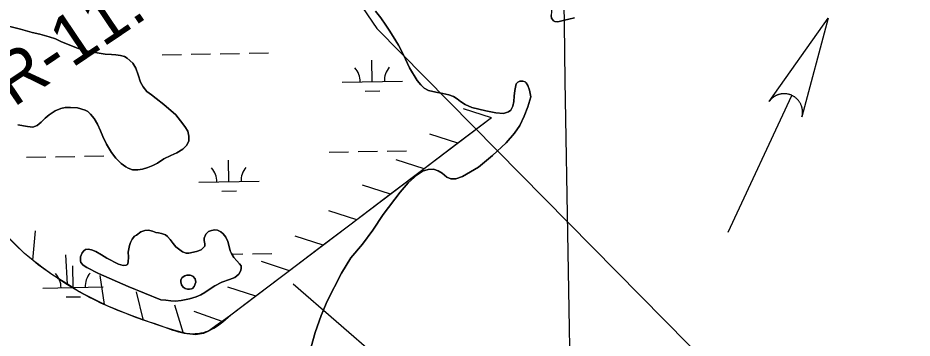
# Model space of a CAD drawing. Extents: x 3892998 to 3931244, y 278583 to 304547.
# Drawn here: x 3912138 to 3913620, y 293140 to 293671 of the extents above; entities that cross this region are included whole.
import ezdxf

# ---------------------------------------------------------------- set-up
doc = ezdxf.new("R2010")
doc.units = 0
for name, color, linetype in [('V-GRID-MAJR', 7, 'Continuous'), ('V-RIVR-RANG-IDEN', 7, 'Continuous'), ('V-RRAP-FSHR', 7, 'Continuous'), ('V-STRM-FLOW', 7, 'Continuous'), ('V-TOPO-SHOR', 7, 'Continuous'), ('V-UTIL-IDEN', 7, 'Continuous'), ('V-UTIL-LINE', 7, 'Continuous'), ('V-WETL-SWMP', 7, 'Continuous')]:
    doc.layers.add(name, color=color, linetype=linetype)

msp = doc.modelspace()

# ---------------------------------------------------------------- linework, layer by layer
at = {"layer": 'V-GRID-MAJR'}
msp.add_spline([(3913205.694, 284291.167), (3913100.856, 290347.625), (3912995.9590000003, 296407.553), (3912891.061, 302467.47500000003), (3912891.001, 302470.95)], degree=3, dxfattribs=at)
at = {"layer": 'V-RRAP-FSHR'}
for p, q in [((3912922.664, 293505.93), (3912876.1720000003, 293520.863)), ((3912866.903, 293463.615), (3912820.4110000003, 293478.548)), ((3912811.1410000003, 293421.3), (3912764.65, 293436.233)), ((3912755.38, 293378.985), (3912708.889, 293393.918)), ((3912699.619, 293336.67100000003), (3912653.127, 293351.604)), ((3912162.119, 293269.672), (3912166.453, 293318.31)), ((3912643.809, 293294.42), (3912597.34, 293309.424)), ((3912219.542, 293229.782), (3912217.167, 293278.555)), ((3912587.983, 293252.19), (3912541.514, 293267.195)), ((3912280.844, 293196.12200000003), (3912274.079, 293244.482)), ((3912345.699, 293169.841), (3912334.42, 293217.351)), ((3912532.157, 293209.961), (3912485.688, 293224.965)), ((3912412.31, 293148.282), (3912397.573, 293194.836)), ((3912476.032, 293168.138), (3912430.011, 293184.461))]:
    msp.add_line(p, q, dxfattribs=at)
for points in [[(3912922.663, 293505.929), (3912685.523, 293325.974), (3912490.434, 293178.4)], [(3912922.663, 293505.929), (3912866.9020000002, 293463.614)], [(3912866.903, 293463.615), (3912811.14, 293421.299)], [(3912811.1410000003, 293421.3), (3912755.379, 293378.985)], [(3912755.38, 293378.985), (3912699.6180000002, 293336.67)], [(3912699.619, 293336.67100000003), (3912685.523, 293325.974), (3912643.808, 293294.419)], [(3912162.119, 293269.672), (3912148.705, 293280.964), (3912127.836, 293301.326), (3912111.333, 293317.787)], [(3912643.809, 293294.42), (3912587.9820000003, 293252.19)], [(3912219.542, 293229.782), (3912195.3680000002, 293245.012), (3912171.199, 293262.028), (3912162.1180000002, 293269.673)], [(3912587.983, 293252.19), (3912532.156, 293209.96)], [(3912280.844, 293196.12200000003), (3912239.383, 293217.281), (3912219.541, 293229.782)], [(3912345.897, 293170.374), (3912333.22, 293174.792), (3912285.646, 293193.672), (3912280.844, 293196.123)], [(3912532.157, 293209.961), (3912490.434, 293178.4), (3912476.032, 293168.138), (3912471.9760000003, 293165.248), (3912453.519, 293152.096), (3912445.484, 293148.107), (3912431.725, 293146.063), (3912417.975, 293147.601), (3912412.509, 293148.988)], [(3912412.5100000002, 293148.988), (3912399.764, 293152.222), (3912381.6610000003, 293157.907), (3912345.896, 293170.374)]]:
    msp.add_lwpolyline(points, dxfattribs=at)
msp.add_spline([(3912490.434, 293178.4), (3912453.519, 293152.096), (3912417.975, 293147.601), (3912381.6610000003, 293157.907), (3912285.646, 293193.672), (3912195.3680000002, 293245.012), (3912148.705, 293280.964), (3912107.2060000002, 293321.903), (3911938.255, 293492.825), (3911757.653, 293671.213), (3911688.061, 293737.987), (3911661.12, 293770.124), (3911612.452, 293841.272)], degree=3, dxfattribs=at)
at = {"layer": 'V-STRM-FLOW'}
msp.add_line((3913315.1484675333, 293315.9066098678), (3913420.8832560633, 293542.8871559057), dxfattribs=at)
msp.add_lwpolyline([(3913383.132331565, 293532.8931758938), (3913480.6751364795, 293671.2438991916), (3913437.521222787, 293507.5572265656), (3913438.140221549, 293510.5372206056), (3913438.4522209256, 293513.4572147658), (3913438.4982208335, 293514.6402123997), (3913438.501220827, 293515.6822103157), (3913438.4562209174, 293516.9472077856), (3913438.364221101, 293518.1632053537), (3913438.2442213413, 293519.21320325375), (3913438.0212217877, 293520.6422003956), (3913437.708222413, 293522.1631973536), (3913437.4992228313, 293523.00519566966), (3913437.193223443, 293524.0831935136), (3913436.732224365, 293525.4851907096), (3913436.3262251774, 293526.5581885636), (3913435.8452261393, 293527.6941862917), (3913435.5032268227, 293528.43318481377), (3913435.104227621, 293529.23318321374), (3913434.587228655, 293530.1931812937), (3913434.0792296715, 293531.06217955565), (3913433.5452307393, 293531.91017785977), (3913433.087231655, 293532.5921764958), (3913432.3722330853, 293533.58217451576), (3913431.6502345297, 293534.5031726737), (3913431.048235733, 293535.22017123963), (3913430.3132372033, 293536.0381696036), (3913429.651238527, 293536.7271682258), (3913429.0452397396, 293537.32016703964), (3913428.5652406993, 293537.7681661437), (3913427.8102422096, 293538.4331648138), (3913427.0152437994, 293539.0901634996), (3913426.241245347, 293539.6871623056), (3913425.434246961, 293540.26816114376), (3913424.6702484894, 293540.78316011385), (3913423.8182501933, 293541.32015903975), (3913423.1052516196, 293541.7381582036), (3913422.065253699, 293542.3041570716), (3913420.8832560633, 293542.8871559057), (3913420.4982568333, 293543.0631555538), (3913419.933257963, 293543.3101550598), (3913419.2542593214, 293543.5891545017), (3913418.590260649, 293543.8441539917), (3913417.9422619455, 293544.07515352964), (3913417.3042632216, 293544.2871531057), (3913416.5442647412, 293544.52015263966), (3913416.010265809, 293544.6701523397), (3913415.2252673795, 293544.87315193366), (3913414.488268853, 293545.0421515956), (3913413.9762698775, 293545.14915138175), (3913412.6522725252, 293545.3831509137), (3913411.9392739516, 293545.48515070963), (3913411.449274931, 293545.5441505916), (3913410.636276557, 293545.62615042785), (3913409.9112780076, 293545.6801503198), (3913409.1522795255, 293545.71815024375), (3913408.2532813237, 293545.7391502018), (3913407.412283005, 293545.7331502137), (3913406.7572843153, 293545.71415025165), (3913406.197285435, 293545.68615030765), (3913405.4362869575, 293545.6311504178), (3913404.7542883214, 293545.56615054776), (3913403.966289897, 293545.4711507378), (3913403.1672914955, 293545.35415097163), (3913402.3642931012, 293545.2131512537), (3913401.351295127, 293545.0051516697), (3913400.6292965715, 293544.83515200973), (3913399.839298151, 293544.62715242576), (3913399.0692996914, 293544.4021528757), (3913398.4523009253, 293544.20515326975), (3913397.7853022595, 293543.9761537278), (3913396.804304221, 293543.60915446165), (3913396.7673042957, 293543.5941544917), (3913396.192305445, 293543.3591549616), (3913395.7693062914, 293543.1781553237), (3913395.1403075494, 293542.89415589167), (3913394.3683090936, 293542.52215663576), (3913393.762310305, 293542.2101572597), (3913393.2223113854, 293541.9181578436), (3913392.538312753, 293541.5281586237), (3913391.8903140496, 293541.1351594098), (3913391.4323149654, 293540.8451599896), (3913390.843316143, 293540.4541607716), (3913390.0473177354, 293539.8931618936), (3913389.5833186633, 293539.5481625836), (3913389.2233193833, 293539.2711631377), (3913388.896320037, 293539.0121636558), (3913388.5113208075, 293538.69816428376), (3913388.013321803, 293538.2751651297), (3913387.5243227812, 293537.8411659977), (3913387.0493237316, 293537.40116687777), (3913386.5873246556, 293536.9551677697), (3913386.004325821, 293536.36416895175), (3913385.661326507, 293536.0021696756), (3913385.1273275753, 293535.41117085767), (3913384.5273287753, 293534.71017225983), (3913384.0933296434, 293534.17417333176), (3913383.774330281, 293533.76417415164), (3913383.4823308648, 293533.3771749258), (3913383.2753312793, 293533.0931754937)], close=True, dxfattribs=at)
at = {"layer": 'V-TOPO-SHOR'}
for points in [[(3912958.6950000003, 293724.89), (3912969.6580000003, 293715.342), (3912979.329, 293706.579), (3912986.001, 293701.367), (3912992.768, 293697.541), (3913000.218, 293695.01), (3913007.861, 293693.273), (3913015.308, 293691.534), (3913018.886, 293689.969), (3913021.681, 293686.816), (3913022.304, 293682.259), (3913021.8510000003, 293675.414), (3913022.275, 293670.759), (3913025.276, 293666.612), (3913027.96, 293665.441), (3913032.521, 293665.17), (3913037.275, 293666.094), (3913043.9080000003, 293667.521), (3913050.736, 293669.348), (3913060.108, 293671.744)], [(3912988.0840000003, 293540.779), (3912985.5360000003, 293551.867), (3912983.21, 293559.586), (3912980.308, 293563.829), (3912978.3170000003, 293565.404), (3912974.94, 293566.473), (3912973.65, 293566.663), (3912969.586, 293566.342), (3912966.324, 293564.835), (3912963.864, 293561.844), (3912961.253, 293551.222), (3912960.421, 293541.401), (3912959.879, 293533.07), (3912958.144, 293524.931), (3912954.615, 293518.267), (3912950.765, 293515.666), (3912942.651, 293513.137), (3912929.761, 293513.852), (3912913.383, 293517.219), (3912889.95, 293523.023), (3912878.917, 293527.713), (3912871.153, 293532.919), (3912865.97, 293537.348), (3912859.9020000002, 293540.979), (3912851.855, 293543.705), (3912842.223, 293545.825), (3912830.312, 293548.33), (3912818.497, 293551.131), (3912811.239, 293554.855), (3912805.455, 293560.37200000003), (3912799.262, 293567.669), (3912786.544, 293588.407), (3912780.406, 293603.042), (3912774.785, 293614.408), (3912768.5670000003, 293626.266), (3912759.953, 293640.49), (3912753.145, 293651.053), (3912747.346, 293659.346), (3912739.043, 293671.488), (3912730.4450000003, 293682.73600000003)], [(3912112.904, 293660.194), (3912141.637, 293652.555), (3912161.454, 293647.238), (3912173.838, 293644.248), (3912189.4930000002, 293640.189), (3912199.702, 293636.691), (3912208.631, 293632.591), (3912218.052, 293628.693), (3912236.202, 293621.386), (3912248.789, 293617.308), (3912259.289, 293614.998), (3912272.162, 293612.805), (3912281.964, 293611.281), (3912292.8510000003, 293610.556), (3912300.073, 293610.405), (3912307.896, 293609.166)], [(3912307.896, 293609.166), (3912314.04, 293607.324), (3912318.806, 293604.58400000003), (3912327.9560000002, 293596.331), (3912332.8570000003, 293588.053), (3912336.881, 293576.998), (3912341.0100000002, 293564.955), (3912345.4110000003, 293557.069), (3912351.295, 293549.587), (3912358.848, 293543.697), (3912366.698, 293538.01), (3912379.6210000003, 293528.098), (3912399.5130000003, 293510.513), (3912407.1890000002, 293500.867), (3912414.269, 293491.612), (3912419.068, 293483.531), (3912421.197, 293475.233), (3912420.946, 293467.714), (3912417.429, 293460.471), (3912410.845, 293453.604), (3912401.086, 293447.808), (3912390.926, 293443.39), (3912379.682, 293437.881), (3912368.7460000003, 293430.691), (3912361.255, 293426.588), (3912353.163, 293423.275), (3912344.176, 293420.846), (3912336.568, 293419.316), (3912327.366, 293419.654), (3912320.131, 293422.181), (3912316.2600000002, 293424.233), (3912308.6070000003, 293429.826), (3912299.651, 293438.674), (3912292.468, 293448.324), (3912284.67, 293461.826), (3912278.356, 293474.84500000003), (3912274.64, 293483.924), (3912269.625, 293495.268), (3912264.224, 293504.732), (3912257.7490000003, 293512.013), (3912253.372, 293515.943), (3912249.202, 293518.388), (3912236.218, 293522.464), (3912224.94, 293522.889), (3912215.838, 293522.832), (3912208.5270000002, 293521.304), (3912199.252, 293517.487), (3912189.599, 293510.702), (3912182.909, 293504.922), (3912176.1240000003, 293498.352), (3912169.529, 293493.167), (3912162.2260000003, 293490.451), (3912153.219, 293491.186), (3912137.472, 293494.156)], [(3912826.327, 293420.344), (3912834.4220000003, 293417.831), (3912840.853, 293413.831), (3912848.779, 293407.18), (3912855.3000000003, 293404.263), (3912863.475, 293404.806), (3912874.686, 293408.523), (3912901.1010000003, 293423.86), (3912924.139, 293443.319), (3912947.069, 293464.352), (3912960.8680000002, 293480.006), (3912969.951, 293493.071), (3912976.951, 293508.48600000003), (3912982.767, 293524.092), (3912988.0840000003, 293540.779)], [(3912621.0640000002, 293116.151), (3912630.515, 293149.517), (3912640.589, 293177.763), (3912650.494, 293201.67100000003), (3912674.1520000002, 293248.232), (3912689.3710000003, 293273.357), (3912708.937, 293296.438), (3912726.1410000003, 293319.308), (3912743.125, 293345.627), (3912771.278, 293382.262), (3912784.683, 293397.816), (3912799.2830000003, 293411.308), (3912808.312, 293417.276), (3912817.852, 293420.293), (3912826.327, 293420.344)], [(3912374.333, 293203.89900000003), (3912320.272, 293226.222), (3912271.165, 293247.388), (3912252.0100000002, 293257.264), (3912245.852, 293261.282), (3912241.864, 293265.908), (3912241.1580000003, 293268.278), (3912241.215, 293274.907), (3912244.142, 293281.555), (3912246.691, 293285.33), (3912249.45, 293287.226), (3912254.193, 293288.148), (3912259.643, 293286.993), (3912266.588, 293283.771), (3912276.318, 293278.389), (3912284.96, 293272.802), (3912304.216, 293262.83), (3912312.242, 293260.901), (3912316.792, 293261.227), (3912319.455, 293262.628), (3912320.522, 293266.195), (3912320.663, 293275.004), (3912320.419, 293282.718), (3912322.525, 293294.109), (3912324.1780000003, 293298.771), (3912327.012, 293304.427), (3912331.0360000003, 293309.697), (3912333.9960000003, 293311.29600000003), (3912341.483, 293316.39), (3912347.9, 293318.903), (3912354.029, 293319.337), (3912360.5700000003, 293317.795), (3912366.223, 293315.751), (3912370.579, 293314.987), (3912375.435, 293314.026), (3912382.177, 293311.694), (3912385.654, 293309.14400000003), (3912389.744, 293303.825), (3912395.0300000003, 293297.032), (3912399.515, 293291.816), (3912410.648, 293283.376), (3912416.698, 293281.135), (3912420.952, 293281.36100000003), (3912433.5, 293284.011), (3912441.301, 293286.532), (3912447.2970000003, 293292.803), (3912447.572, 293296.565), (3912446.548, 293301.998), (3912446.523, 293306.156), (3912449.3510000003, 293312.701), (3912453.578, 293317.18), (3912458.315, 293319.091), (3912464.2460000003, 293320.017), (3912468.703, 293319.351), (3912474.06, 293316.81200000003), (3912478.04, 293313.375), (3912482.328, 293307.958), (3912485.4390000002, 293300.657), (3912487.669, 293292.162), (3912489.298, 293284.85000000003), (3912491.896, 293280.61100000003), (3912495.4990000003, 293274.004), (3912500.2830000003, 293268.294), (3912504.862, 293263.674), (3912507.457, 293260.127), (3912507.973, 293256.469), (3912507.111, 293252.31), (3912503.7830000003, 293246.254), (3912497.088, 293240.87), (3912488.302, 293237.55), (3912475.469, 293232.919), (3912464.228, 293227.013), (3912456.142, 293222.212), (3912447.377, 293215.827), (3912441.0670000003, 293212.226), (3912433.272, 293208.814), (3912421.816, 293205.38), (3912408.475, 293202.625), (3912398.983, 293201.874), (3912390.967, 293202.023), (3912382.65, 293203.059), (3912374.333, 293203.89900000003)], [(3912429.901, 293225.909), (3912432.328, 293233.24700000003), (3912431.2060000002, 293238.781), (3912427.321, 293243.208), (3912422.957, 293244.964), (3912417.812, 293244.833), (3912414.156, 293243.919), (3912409.722, 293241.12200000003), (3912407.668, 293237.251), (3912407.593, 293233.589), (3912408.909, 293228.453), (3912411.504, 293224.70900000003), (3912414.7830000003, 293222.452), (3912418.748, 293221.389), (3912422.309, 293221.412), (3912425.177, 293221.924), (3912426.756, 293222.427), (3912429.901, 293225.909)]]:
    msp.add_lwpolyline(points, dxfattribs=at)
at = {"layer": 'V-UTIL-LINE'}
msp.add_line((3913277.915, 292637.723), (3912593.866, 293229.884), dxfattribs=at)
msp.add_lwpolyline([(3906680.9470508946, 302363.4542383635), (3908344.9110000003, 300089.976), (3912732.592, 293653.732), (3913646.809, 292726.848), (3916248.696, 289346.047), (3918159.8680000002, 287579.415), (3921518.269458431, 284435.0583118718)], dxfattribs=at)
at = {"layer": 'V-WETL-SWMP'}
for p, q in [((3912424.976413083, 293611.1753321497), (3912456.9716198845, 293611.7291742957)), ((3912472.969223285, 293612.00609536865), (3912504.9644300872, 293612.55993751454)), ((3912520.962033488, 293612.8368585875), (3912552.9572402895, 293613.3907007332)), ((3912376.98360288, 293610.3445689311), (3912408.978809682, 293610.89841107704)), ((3912725.125799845, 293565.6213644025), (3912724.5027274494, 293601.61597205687)), ((3912675.133289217, 293564.7559860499), (3912775.1183104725, 293566.4867427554)), ((3912713.394670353, 293549.984984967), (3912737.3910754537, 293550.4003665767)), ((3912653.726642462, 293448.93614077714), (3912685.7218492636, 293449.489982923)), ((3912701.7194526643, 293449.766903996), (3912733.714659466, 293450.32074614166)), ((3912749.712262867, 293450.59766721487), (3912781.7074696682, 293451.1515093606)), ((3912151.8938219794, 293440.2493344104), (3912183.8890287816, 293440.80317655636)), ((3912199.886632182, 293441.08009762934), (3912231.8818389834, 293441.633939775)), ((3912247.879442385, 293441.9108608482), (3912279.874649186, 293442.46470299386)), ((3912487.491256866, 293399.6216240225), (3912486.8681844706, 293435.61623167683)), ((3912437.4987462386, 293398.7562456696), (3912537.483767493, 293400.4870023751)), ((3912475.760127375, 293383.98524458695), (3912499.7565324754, 293384.40062619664)), ((3912492.437372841, 293279.6182543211), (3912510.722224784, 293279.9347680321)), ((3912526.719828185, 293280.211689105), (3912558.7150349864, 293280.76553125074)), ((3912229.0507740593, 293224.3093885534), (3912228.427701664, 293260.3039962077)), ((3912179.058263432, 293223.44401020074), (3912279.0432846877, 293225.17476690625)), ((3912217.3196445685, 293208.67300911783), (3912241.3160496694, 293209.0883907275))]:
    msp.add_line(p, q, dxfattribs=at)
for points in [[(3912730.446, 293682.73600000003), (3912739.042, 293671.488), (3912747.345, 293659.346), (3912753.146, 293651.054), (3912759.952, 293640.489), (3912768.566, 293626.266), (3912774.785, 293614.408), (3912780.407, 293603.043), (3912786.545, 293588.408), (3912799.2630000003, 293567.668), (3912805.455, 293560.371), (3912811.238, 293554.855), (3912818.498, 293551.132), (3912830.313, 293548.33), (3912842.224, 293545.826), (3912851.8540000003, 293543.705)], [(3913060.108, 293671.744), (3913050.737, 293669.348), (3913043.9080000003, 293667.521), (3913037.275, 293666.093), (3913032.522, 293665.17100000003), (3913027.96, 293665.44), (3913025.276, 293666.613), (3913022.276, 293670.759), (3913021.8510000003, 293675.415)], [(3912137.471, 293494.156), (3912153.218, 293491.18700000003), (3912162.225, 293490.451), (3912169.528, 293493.167), (3912176.1240000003, 293498.352), (3912182.909, 293504.922), (3912189.6, 293510.701), (3912199.252, 293517.487), (3912208.5270000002, 293521.304), (3912215.838, 293522.833), (3912224.9390000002, 293522.889), (3912236.218, 293522.464), (3912249.202, 293518.389), (3912253.372, 293515.942), (3912257.7490000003, 293512.012), (3912264.224, 293504.732), (3912269.6240000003, 293495.26900000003), (3912274.64, 293483.924), (3912278.356, 293474.846), (3912284.669, 293461.827), (3912292.468, 293448.32300000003), (3912299.65, 293438.673), (3912308.6070000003, 293429.826), (3912316.259, 293424.234), (3912320.13, 293422.181), (3912327.366, 293419.653), (3912336.568, 293419.315), (3912344.176, 293420.84500000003), (3912353.163, 293423.275), (3912361.254, 293426.589), (3912368.747, 293430.691), (3912379.682, 293437.881), (3912390.926, 293443.391), (3912401.0870000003, 293447.80700000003), (3912410.845, 293453.604), (3912417.43, 293460.471), (3912420.946, 293467.714), (3912421.197, 293475.233), (3912419.068, 293483.53), (3912414.27, 293491.612), (3912407.1890000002, 293500.867), (3912399.5130000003, 293510.513), (3912379.62, 293528.098), (3912366.699, 293538.009), (3912358.849, 293543.69800000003), (3912351.295, 293549.587), (3912345.412, 293557.068), (3912341.011, 293564.955), (3912336.881, 293576.998), (3912332.856, 293588.052), (3912327.957, 293596.331), (3912318.805, 293604.58400000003), (3912314.04, 293607.325), (3912307.896, 293609.166), (3912300.073, 293610.404), (3912292.8510000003, 293610.55700000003), (3912281.965, 293611.281), (3912272.163, 293612.804), (3912259.289, 293614.999), (3912248.789, 293617.309), (3912236.201, 293621.386), (3912218.0530000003, 293628.693), (3912208.632, 293632.591), (3912199.703, 293636.691), (3912189.4930000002, 293640.189), (3912173.838, 293644.24700000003), (3912161.454, 293647.237), (3912141.637, 293652.555), (3912112.903, 293660.193)], [(3912851.8540000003, 293543.705), (3912859.901, 293540.979), (3912865.97, 293537.348), (3912871.153, 293532.919), (3912878.917, 293527.713), (3912889.95, 293523.023), (3912913.382, 293517.219), (3912929.7600000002, 293513.851), (3912942.6520000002, 293513.137), (3912950.7660000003, 293515.666), (3912954.616, 293518.267), (3912958.144, 293524.931), (3912959.878, 293533.071), (3912960.421, 293541.401), (3912961.253, 293551.221), (3912963.864, 293561.844), (3912966.324, 293564.83400000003), (3912969.586, 293566.341), (3912973.649, 293566.663), (3912974.9390000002, 293566.473), (3912978.316, 293565.403), (3912980.308, 293563.83), (3912983.2090000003, 293559.585), (3912985.537, 293551.866), (3912988.0840000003, 293540.779), (3912982.767, 293524.092), (3912976.951, 293508.48600000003), (3912969.951, 293493.07), (3912960.867, 293480.006), (3912947.069, 293464.351), (3912924.139, 293443.318), (3912901.1010000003, 293423.86100000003), (3912874.687, 293408.522), (3912863.4760000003, 293404.806), (3912855.3000000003, 293404.263), (3912848.778, 293407.179), (3912840.8540000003, 293413.831), (3912834.423, 293417.832), (3912826.327, 293420.344), (3912817.853, 293420.292), (3912808.313, 293417.277), (3912799.2830000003, 293411.308), (3912784.683, 293397.816), (3912771.279, 293382.262), (3912743.1240000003, 293345.626), (3912726.14, 293319.308), (3912708.937, 293296.438), (3912689.3710000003, 293273.357), (3912674.153, 293248.232), (3912650.494, 293201.67100000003), (3912640.59, 293177.762), (3912630.5160000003, 293149.516), (3912621.0640000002, 293116.15)]]:
    msp.add_lwpolyline(points, dxfattribs=at)
for points in [[(3912398.9820000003, 293201.874), (3912408.4760000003, 293202.626), (3912421.816, 293205.379), (3912433.272, 293208.814), (3912441.0670000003, 293212.226), (3912447.377, 293215.827), (3912456.143, 293222.213), (3912464.227, 293227.012), (3912475.469, 293232.919), (3912488.3030000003, 293237.55), (3912497.088, 293240.869), (3912503.7830000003, 293246.253), (3912507.11, 293252.309), (3912507.974, 293256.47000000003), (3912507.457, 293260.128), (3912504.863, 293263.674), (3912500.2830000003, 293268.295), (3912495.4990000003, 293274.004), (3912491.896, 293280.61100000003), (3912489.2970000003, 293284.85000000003), (3912487.669, 293292.161), (3912485.44, 293300.656), (3912482.328, 293307.95900000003), (3912478.04, 293313.374), (3912474.061, 293316.81200000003), (3912468.702, 293319.352), (3912464.2460000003, 293320.017), (3912458.315, 293319.09), (3912453.578, 293317.181), (3912449.3510000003, 293312.702), (3912446.522, 293306.155), (3912446.548, 293301.999), (3912447.571, 293296.564), (3912447.2970000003, 293292.802), (3912441.301, 293286.532), (3912433.5, 293284.01), (3912420.951, 293281.36100000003), (3912416.698, 293281.136), (3912410.648, 293283.375), (3912399.515, 293291.815), (3912395.0300000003, 293297.031), (3912389.745, 293303.825), (3912385.6550000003, 293309.143), (3912382.177, 293311.694), (3912375.434, 293314.027), (3912370.58, 293314.98600000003), (3912366.222, 293315.751), (3912360.5700000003, 293317.794), (3912354.0300000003, 293319.336), (3912347.899, 293318.903), (3912341.483, 293316.39), (3912333.995, 293311.297), (3912331.037, 293309.696), (3912327.012, 293304.427), (3912324.1780000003, 293298.77), (3912322.525, 293294.11), (3912320.419, 293282.719), (3912320.664, 293275.003), (3912320.521, 293266.196), (3912319.454, 293262.628), (3912316.792, 293261.226), (3912312.242, 293260.901), (3912304.216, 293262.83), (3912284.96, 293272.803), (3912276.318, 293278.39), (3912266.588, 293283.771), (3912259.643, 293286.993), (3912254.194, 293288.147), (3912249.45, 293287.227), (3912246.6920000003, 293285.33), (3912244.142, 293281.555), (3912241.215, 293274.908), (3912241.157, 293268.278), (3912241.864, 293265.908), (3912245.8510000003, 293261.283), (3912252.0100000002, 293257.264), (3912271.166, 293247.389), (3912320.273, 293226.222), (3912374.333, 293203.89900000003), (3912382.649, 293203.06), (3912390.967, 293202.023)], [(3912429.901, 293225.91000000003), (3912426.756, 293222.428), (3912425.176, 293221.923), (3912422.31, 293221.411), (3912418.7490000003, 293221.389), (3912414.784, 293222.453), (3912411.505, 293224.708), (3912408.91, 293228.452), (3912407.592, 293233.589), (3912407.668, 293237.25), (3912409.722, 293241.121), (3912414.157, 293243.919), (3912417.812, 293244.832), (3912422.9560000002, 293244.963), (3912427.321, 293243.20900000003), (3912431.207, 293238.78), (3912432.329, 293233.24700000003)]]:
    msp.add_lwpolyline(points, close=True, dxfattribs=at)
for centre, radius, start, end in [((3912669.8829207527, 293565.13997564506), 35.24628790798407, 0.21988000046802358, 41.76353833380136), ((3912780.352243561, 293567.0522172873), 35.24628790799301, 140.21987699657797, 181.7635353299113), ((3912432.2483777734, 293399.140235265), 35.24628790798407, 0.21988000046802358, 41.76353833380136), ((3912542.717700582, 293401.05247690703), 35.24628790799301, 140.21987699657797, 181.7635353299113), ((3912173.807894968, 293223.8279997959), 35.24628790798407, 0.21988000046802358, 41.76353833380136), ((3912284.277217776, 293225.74024143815), 35.24628790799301, 140.21987699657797, 181.7635353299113)]:
    msp.add_arc(centre, radius, start, end, dxfattribs=at)

# ---------------------------------------------------------------- texts
at = {"layer": 'V-RIVR-RANG-IDEN'}
msp.add_text('R-11.6', height=82.99999800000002, rotation=33.95530346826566, dxfattribs=at).set_placement((3912130.0096840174, 293522.08375447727))
at = {"layer": 'V-UTIL-IDEN'}
msp.add_text('PEOPLES UTILITIES INC.', height=82.99983200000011, rotation=34.22789159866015, dxfattribs=at).set_placement((3913644.44819546, 292889.2472603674))

doc.saveas('drawing.dxf')
